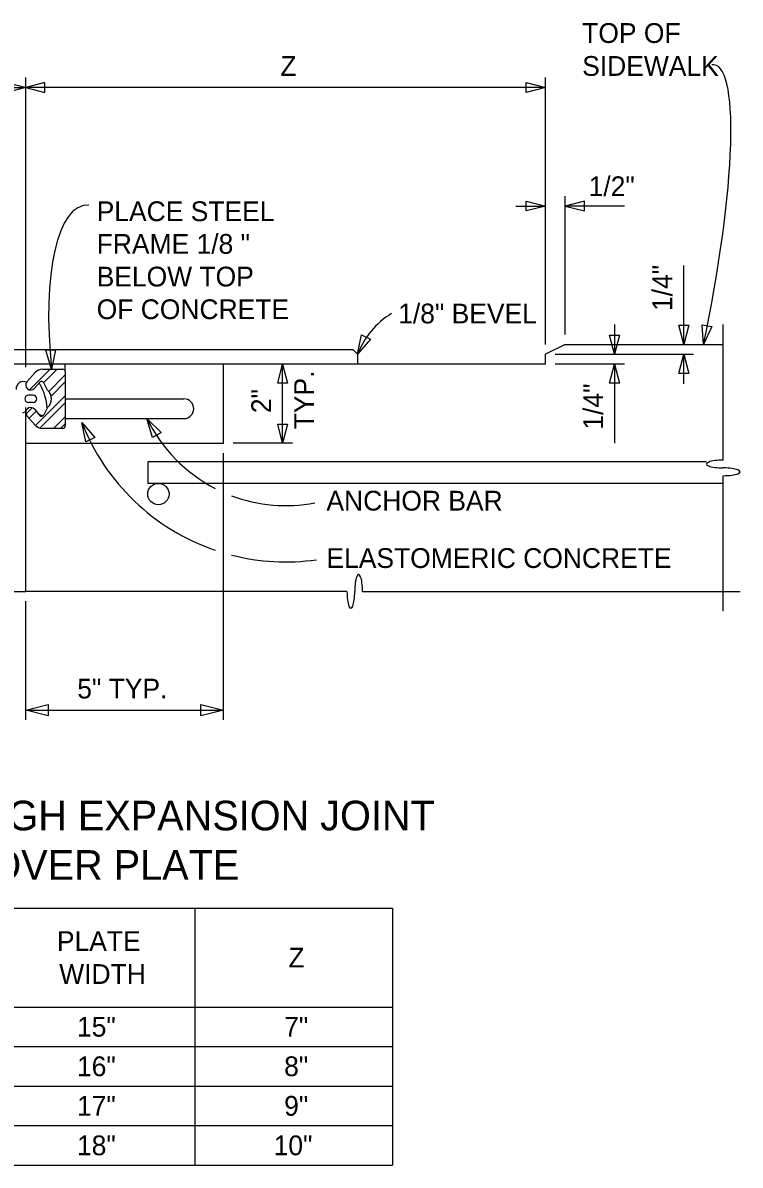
# Model space of a CAD drawing. Extents: x 19590 to 20151, y 19944 to 20103.
# Drawn here: x 19691.75 to 19708.54, y 20042.3 to 20069.02 of the extents above; entities that cross this region are included whole.
import ezdxf

# ---------------------------------------------------------------- set-up
doc = ezdxf.new("R2010")
doc.units = 0
for name, color, linetype in [('Default', 7, 'Continuous'), ('DETAIL_PR', 7, 'Continuous'), ('DETAIL_TEXT_DIMEN_PR', 7, 'Continuous'), ('Level 1', 7, 'Continuous')]:
    doc.layers.add(name, color=color, linetype=linetype)

# ---------------------------------------------------------------- blocks, each defined once
blk = doc.blocks.new('_X7')
at = {"layer": 'Default'}
for p, q in [((8.051, 16.889), (8.594, 17.433)), ((8.426, 17.08), (8.778, 17.433)), ((8.56, 16.847), (8.995, 17.282)), ((8.622, 16.724), (8.995, 17.098)), ((8.213, 15.947), (8.995, 16.729)), ((7.96, 16.247), (8.125, 16.412)), ((8.04, 16.142), (8.224, 16.326)), ((8.329, 15.879), (8.995, 16.545)), ((8.689, 15.87), (8.995, 16.177)), ((8.873, 15.87), (8.995, 15.993))]:
    blk.add_line(p, q, dxfattribs=at)

msp = doc.modelspace()

# ---------------------------------------------------------------- linework, layer by layer
at = {"layer": 'DETAIL_PR'}
for p, q in [((19704.444, 20061.498), (19703.981, 20061.267)), ((19704.444, 20061.498), (19703.981, 20061.267)), ((19704.444, 20061.498), (19708.144, 20061.498)), ((19704.444, 20061.498), (19708.144, 20061.498)), ((19682.937, 20061.383), (19699.472, 20061.383)), ((19682.937, 20061.383), (19699.472, 20061.383)), ((19699.472, 20061.383), (19699.587, 20061.267)), ((19699.472, 20061.383), (19699.587, 20061.267)), ((19699.587, 20061.267), (19699.587, 20061.036)), ((19699.587, 20061.267), (19699.587, 20061.036)), ((19703.981, 20061.036), (19703.981, 20061.267)), ((19703.981, 20061.036), (19703.981, 20061.267)), ((19699.587, 20061.036), (19682.937, 20061.036)), ((19699.587, 20061.036), (19682.937, 20061.036)), ((19692.213, 20060.92), (19692.687, 20060.92)), ((19692.213, 20060.92), (19692.687, 20060.92)), ((19692.745, 20060.862), (19692.745, 20061.036)), ((19692.745, 20060.862), (19692.745, 20061.036)), ((19696.445, 20059.186), (19696.445, 20061.036)), ((19696.445, 20059.186), (19696.445, 20061.036)), ((19703.981, 20061.036), (19699.587, 20061.036)), ((19703.981, 20061.036), (19699.587, 20061.036)), ((19691.849, 20060.626), (19692.04, 20060.842)), ((19691.849, 20060.626), (19692.04, 20060.842)), ((19692.745, 20060.862), (19692.745, 20060.226)), ((19692.745, 20060.862), (19692.745, 20060.226)), ((19692.022, 20060.473), (19692.147, 20060.614)), ((19692.022, 20060.473), (19692.147, 20060.614)), ((19692.328, 20060.43), (19692.242, 20060.602)), ((19692.328, 20060.43), (19692.242, 20060.602)), ((19691.99, 20060.313), (19691.885, 20060.313)), ((19691.99, 20060.313), (19691.885, 20060.313)), ((19691.99, 20060.14), (19691.885, 20060.14)), ((19691.99, 20060.14), (19691.885, 20060.14)), ((19692.745, 20060.226), (19695.52, 20060.226)), ((19692.745, 20060.226), (19692.745, 20059.764)), ((19692.745, 20060.226), (19695.52, 20060.226)), ((19692.745, 20060.226), (19692.745, 20059.764)), ((19691.752, 20059.9), (19691.822, 20059.926)), ((19691.752, 20059.9), (19691.822, 20059.926)), ((19691.82, 20055.72), (19691.82, 20060.019)), ((19691.82, 20055.72), (19691.82, 20060.019)), ((19692.022, 20059.98), (19692.147, 20059.839)), ((19692.022, 20059.98), (19692.147, 20059.839)), ((19692.112, 20059.879), (19692.154, 20059.854)), ((19692.112, 20059.879), (19692.154, 20059.854)), ((19692.328, 20060.023), (19692.242, 20059.851)), ((19692.328, 20060.023), (19692.242, 20059.851)), ((19691.849, 20059.827), (19692.04, 20059.611)), ((19691.849, 20059.827), (19692.04, 20059.611)), ((19692.745, 20059.764), (19695.52, 20059.764)), ((19692.745, 20059.764), (19692.745, 20059.591)), ((19692.745, 20059.764), (19695.52, 20059.764)), ((19692.745, 20059.764), (19692.745, 20059.591)), ((19692.687, 20059.533), (19692.213, 20059.533)), ((19692.687, 20059.533), (19692.213, 20059.533)), ((19691.82, 20059.186), (19696.445, 20059.186)), ((19691.82, 20059.186), (19696.445, 20059.186)), ((19707.749, 20058.748), (19694.675, 20058.748)), ((19694.675, 20058.748), (19694.675, 20058.248)), ((19707.749, 20058.748), (19694.675, 20058.748)), ((19694.675, 20058.748), (19694.675, 20058.248)), ((19708.144, 20058.248), (19694.675, 20058.248)), ((19708.144, 20058.248), (19694.675, 20058.248))]:
    msp.add_line(p, q, dxfattribs=at)
msp.add_circle((19694.925, 20057.998), 0.25, dxfattribs=at)
msp.add_circle((19694.925, 20057.998), 0.25, dxfattribs=at)
for centre, radius, start, end in [((19692.213, 20060.689), 0.231, 90, 138.538), ((19692.213, 20060.689), 0.231, 90, 138.538), ((19692.687, 20060.862), 0.0578, 0, 90), ((19692.687, 20060.862), 0.0578, 0, 90), ((19691.765, 20060.456), 0.173, 64.7625, 184.3545), ((19691.765, 20060.456), 0.173, 64.7625, 184.3545), ((19691.935, 20060.549), 0.116, 138.538, 318.538), ((19691.935, 20060.549), 0.116, 138.538, 318.538), ((19692.107, 20060.533), 0.0578, 28.7472, 73.3345), ((19692.107, 20060.533), 0.0578, 28.7472, 73.3345), ((19692.19, 20060.576), 0.0578, 26.8091, 138.538), ((19692.19, 20060.576), 0.0578, 26.8091, 138.538), ((19690.942, 20059.893), 1.388, 4.9857, 28.7472), ((19690.942, 20059.893), 1.388, 4.9857, 28.7472), ((19692.151, 20060.226), 0.27, 311.1121, 48.8879), ((19692.151, 20060.226), 0.27, 311.1121, 48.8879), ((19691.885, 20060.226), 0.0867, 90, 270), ((19691.885, 20060.226), 0.0867, 90, 270), ((19691.99, 20060.226), 0.0867, 270, 90), ((19691.99, 20060.226), 0.0867, 270, 90), ((19695.52, 20059.995), 0.231, 270, 90), ((19695.52, 20059.995), 0.231, 270, 90), ((19691.935, 20059.904), 0.116, 41.462, 180), ((19691.935, 20059.904), 0.116, 41.462, 180), ((19691.935, 20059.904), 0.116, 180, 221.462), ((19691.935, 20059.904), 0.116, 180, 221.462), ((19692.19, 20059.877), 0.0578, 221.462, 333.1909), ((19692.19, 20059.877), 0.0578, 221.462, 333.1909), ((19692.212, 20059.954), 0.116, 240, 281.5069), ((19692.212, 20059.954), 0.116, 240, 281.5069), ((19692.213, 20059.764), 0.231, 221.462, 270), ((19692.213, 20059.764), 0.231, 221.462, 270), ((19692.687, 20059.591), 0.0578, 270, 0), ((19692.687, 20059.591), 0.0578, 270, 0)]:
    msp.add_arc(centre, radius, start, end, dxfattribs=at)
for centre, major_axis, ratio, start_param, end_param in [((19708.144, 20058.7), (0.395, 0), 0.230204, 1.570796, 4.712389), ((19708.144, 20058.7), (0.395, 0), 0.230204, 1.570796, 4.712389), ((19708.144, 20058.518), (0.395, 0), 0.230206, 4.712389, 7.853982), ((19708.144, 20058.518), (0.395, 0), 0.230206, 4.712389, 7.853982), ((19699.61, 20055.72), (0, -0.395), 0.230204, 1.570796, 4.712389), ((19699.61, 20055.72), (0, -0.395), 0.230204, 1.570796, 4.712389), ((19699.428, 20055.72), (0, -0.395), 0.230206, 4.712389, 7.853982), ((19699.428, 20055.72), (0, -0.395), 0.230206, 4.712389, 7.853982)]:
    msp.add_ellipse(centre, major_axis=major_axis, ratio=ratio, start_param=start_param, end_param=end_param, dxfattribs=at)
at = {"layer": 'DETAIL_TEXT_DIMEN_PR'}
for p, q in [((19691.372, 20067.626), (19691.82, 20067.511)), ((19691.372, 20067.626), (19691.82, 20067.511)), ((19691.82, 20060.967), (19691.82, 20067.742)), ((19691.82, 20060.967), (19691.82, 20067.742)), ((19692.268, 20067.626), (19691.82, 20067.511)), ((19692.268, 20067.626), (19691.82, 20067.511)), ((19692.268, 20067.395), (19692.268, 20067.626)), ((19692.268, 20067.395), (19692.268, 20067.626)), ((19703.533, 20067.395), (19703.533, 20067.626)), ((19703.533, 20067.626), (19703.981, 20067.511)), ((19703.533, 20067.395), (19703.533, 20067.626)), ((19703.533, 20067.626), (19703.981, 20067.511)), ((19703.981, 20061.498), (19703.981, 20067.742)), ((19703.981, 20061.498), (19703.981, 20067.742)), ((19689.412, 20067.511), (19691.82, 20067.511)), ((19689.412, 20067.511), (19691.82, 20067.511)), ((19691.82, 20067.511), (19691.372, 20067.395)), ((19691.82, 20067.511), (19691.372, 20067.395)), ((19703.981, 20067.511), (19691.82, 20067.511)), ((19691.82, 20067.511), (19692.268, 20067.395)), ((19703.981, 20067.511), (19691.82, 20067.511)), ((19691.82, 20067.511), (19692.268, 20067.395)), ((19703.981, 20067.511), (19703.533, 20067.395)), ((19703.981, 20067.511), (19703.533, 20067.395)), ((19704.444, 20061.73), (19704.444, 20064.967)), ((19704.444, 20061.73), (19704.444, 20064.967)), ((19703.533, 20064.62), (19703.533, 20064.851)), ((19703.533, 20064.851), (19703.981, 20064.736)), ((19703.533, 20064.62), (19703.533, 20064.851)), ((19703.533, 20064.851), (19703.981, 20064.736)), ((19703.981, 20064.736), (19703.533, 20064.62)), ((19703.981, 20064.736), (19703.533, 20064.62)), ((19704.892, 20064.851), (19704.444, 20064.736)), ((19704.892, 20064.851), (19704.444, 20064.736)), ((19704.444, 20064.736), (19704.892, 20064.62)), ((19704.444, 20064.736), (19704.892, 20064.62)), ((19704.892, 20064.62), (19704.892, 20064.851)), ((19704.892, 20064.62), (19704.892, 20064.851)), ((19699.587, 20061.267), (19699.679, 20061.721)), ((19699.587, 20061.267), (19699.679, 20061.721)), ((19699.679, 20061.721), (19699.887, 20061.62)), ((19699.679, 20061.721), (19699.887, 20061.62)), ((19705.484, 20061.715), (19705.716, 20061.715)), ((19705.6, 20061.267), (19705.484, 20061.715)), ((19705.484, 20061.715), (19705.716, 20061.715)), ((19705.6, 20061.267), (19705.484, 20061.715)), ((19705.716, 20061.715), (19705.6, 20061.267)), ((19705.716, 20061.715), (19705.6, 20061.267)), ((19707.103, 20061.946), (19707.334, 20061.946)), ((19707.219, 20061.498), (19707.103, 20061.946)), ((19707.103, 20061.946), (19707.334, 20061.946)), ((19707.219, 20061.498), (19707.103, 20061.946)), ((19707.334, 20061.946), (19707.219, 20061.498)), ((19707.334, 20061.946), (19707.219, 20061.498)), ((19707.646, 20061.96), (19707.873, 20061.919)), ((19707.681, 20061.498), (19707.646, 20061.96)), ((19707.646, 20061.96), (19707.873, 20061.919)), ((19707.681, 20061.498), (19707.646, 20061.96)), ((19707.873, 20061.919), (19707.681, 20061.498)), ((19707.873, 20061.919), (19707.681, 20061.498)), ((19708.144, 20058.791), (19708.144, 20061.961)), ((19708.144, 20058.791), (19708.144, 20061.961)), ((19699.887, 20061.62), (19699.587, 20061.267)), ((19699.887, 20061.62), (19699.587, 20061.267)), ((19692.286, 20061.361), (19692.517, 20061.374)), ((19692.286, 20061.361), (19692.517, 20061.374)), ((19692.425, 20060.92), (19692.286, 20061.361)), ((19692.425, 20060.92), (19692.286, 20061.361)), ((19692.517, 20061.374), (19692.425, 20060.92)), ((19692.517, 20061.374), (19692.425, 20060.92)), ((19704.212, 20061.267), (19707.45, 20061.267)), ((19704.212, 20061.267), (19707.45, 20061.267)), ((19707.103, 20060.819), (19707.219, 20061.267)), ((19707.103, 20060.819), (19707.219, 20061.267)), ((19707.219, 20061.267), (19707.334, 20060.819)), ((19707.219, 20061.267), (19707.334, 20060.819)), ((19697.717, 20060.588), (19697.832, 20061.036)), ((19697.717, 20060.588), (19697.832, 20061.036)), ((19697.832, 20059.186), (19697.832, 20061.036)), ((19697.832, 20061.036), (19697.948, 20060.588)), ((19697.832, 20059.186), (19697.832, 20061.036)), ((19697.832, 20061.036), (19697.948, 20060.588)), ((19705.831, 20061.036), (19704.212, 20061.036)), ((19705.831, 20061.036), (19704.212, 20061.036)), ((19705.484, 20060.588), (19705.6, 20061.036)), ((19705.484, 20060.588), (19705.6, 20061.036)), ((19705.6, 20061.036), (19705.716, 20060.588)), ((19705.6, 20061.036), (19705.716, 20060.588)), ((19707.334, 20060.819), (19707.103, 20060.819)), ((19707.334, 20060.819), (19707.103, 20060.819)), ((19697.948, 20060.588), (19697.717, 20060.588)), ((19697.948, 20060.588), (19697.717, 20060.588)), ((19705.716, 20060.588), (19705.484, 20060.588)), ((19705.716, 20060.588), (19705.484, 20060.588)), ((19693.228, 20059.219), (19693.131, 20059.672)), ((19693.131, 20059.672), (19693.435, 20059.323)), ((19693.228, 20059.219), (19693.131, 20059.672)), ((19693.131, 20059.672), (19693.435, 20059.323)), ((19694.788, 20059.32), (19694.657, 20059.764)), ((19694.657, 20059.764), (19694.986, 20059.439)), ((19694.788, 20059.32), (19694.657, 20059.764)), ((19694.657, 20059.764), (19694.986, 20059.439)), ((19697.717, 20059.634), (19697.948, 20059.634)), ((19697.832, 20059.186), (19697.717, 20059.634)), ((19697.717, 20059.634), (19697.948, 20059.634)), ((19697.832, 20059.186), (19697.717, 20059.634)), ((19697.948, 20059.634), (19697.832, 20059.186)), ((19697.948, 20059.634), (19697.832, 20059.186)), ((19693.435, 20059.323), (19693.228, 20059.219)), ((19693.435, 20059.323), (19693.228, 20059.219)), ((19694.986, 20059.439), (19694.788, 20059.32)), ((19694.986, 20059.439), (19694.788, 20059.32)), ((19698.063, 20059.186), (19696.676, 20059.186)), ((19698.063, 20059.186), (19696.676, 20059.186)), ((19696.445, 20052.714), (19696.445, 20058.955)), ((19696.445, 20052.714), (19696.445, 20058.955)), ((19708.144, 20055.258), (19708.144, 20058.427)), ((19708.144, 20055.258), (19708.144, 20058.427)), ((19699.337, 20055.72), (19691.82, 20055.72)), ((19699.337, 20055.72), (19691.82, 20055.72)), ((19699.701, 20055.72), (19708.538, 20055.72)), ((19699.701, 20055.72), (19708.538, 20055.72)), ((19691.82, 20052.714), (19691.82, 20055.489)), ((19691.82, 20052.714), (19691.82, 20055.489)), ((19691.82, 20052.945), (19696.445, 20052.945)), ((19691.82, 20052.945), (19696.445, 20052.945)), ((19686.526, 20048.311), (19700.401, 20048.311)), ((19686.526, 20048.311), (19700.401, 20048.311)), ((19695.776, 20048.311), (19695.776, 20042.298)), ((19695.776, 20048.311), (19695.776, 20042.298)), ((19700.401, 20048.311), (19700.401, 20042.298)), ((19700.401, 20048.311), (19700.401, 20042.298)), ((19686.526, 20045.998), (19700.401, 20045.998)), ((19686.526, 20045.998), (19700.401, 20045.998)), ((19686.526, 20045.073), (19700.401, 20045.073)), ((19686.526, 20045.073), (19700.401, 20045.073)), ((19686.526, 20044.148), (19700.401, 20044.148)), ((19686.526, 20044.148), (19700.401, 20044.148)), ((19686.526, 20043.223), (19700.401, 20043.223)), ((19686.526, 20043.223), (19700.401, 20043.223)), ((19686.526, 20042.298), (19700.401, 20042.298)), ((19686.526, 20042.298), (19700.401, 20042.298))]:
    msp.add_line(p, q, dxfattribs=at)
for centre, radius, start, end in [((19697.907, 20061.539), 5.128, 201.3572, 251.1723), ((19697.907, 20061.539), 5.128, 201.3572, 251.1723), ((19697.907, 20061.339), 3.611, 205.8637, 242.7252), ((19697.907, 20061.339), 3.611, 205.8637, 242.7252), ((19697.907, 20061.339), 3.611, 249.4192, 280.7711), ((19697.907, 20061.339), 3.611, 249.4192, 280.7711), ((19697.907, 20061.539), 5.128, 255.6669, 278.0265), ((19697.907, 20061.539), 5.128, 255.6669, 278.0265)]:
    msp.add_arc(centre, radius, start, end, dxfattribs=at)
msp.add_ellipse((19693.849, 20060.491), major_axis=(-0.659, 4.259), ratio=0.314674, start_param=6.20772, end_param=7.704615, dxfattribs=at)
msp.add_ellipse((19693.849, 20060.491), major_axis=(-0.659, 4.259), ratio=0.314674, start_param=6.20772, end_param=7.704615, dxfattribs=at)
at = {"layer": 'Level 1'}
for p, q in [((19703.287, 20064.736), (19703.981, 20064.736)), ((19703.287, 20064.736), (19703.981, 20064.736)), ((19705.831, 20064.736), (19704.444, 20064.736)), ((19705.831, 20064.736), (19704.444, 20064.736)), ((19707.219, 20061.498), (19707.219, 20063.348)), ((19707.219, 20061.498), (19707.219, 20063.348)), ((19705.6, 20061.961), (19705.6, 20061.267)), ((19705.6, 20061.961), (19705.6, 20061.267)), ((19707.219, 20060.573), (19707.219, 20061.267)), ((19707.219, 20060.573), (19707.219, 20061.267)), ((19705.6, 20061.036), (19705.6, 20059.186)), ((19705.6, 20061.036), (19705.6, 20059.186)), ((19689.412, 20055.72), (19691.82, 20055.72)), ((19689.412, 20055.72), (19691.82, 20055.72)), ((19691.82, 20052.945), (19692.344, 20053.077)), ((19691.82, 20052.945), (19692.344, 20053.077)), ((19692.344, 20052.813), (19691.82, 20052.945)), ((19692.344, 20052.813), (19691.82, 20052.945)), ((19692.344, 20053.077), (19692.344, 20052.813)), ((19692.344, 20053.077), (19692.344, 20052.813)), ((19695.921, 20053.077), (19696.445, 20052.945)), ((19695.921, 20052.813), (19695.921, 20053.077)), ((19695.921, 20053.077), (19696.445, 20052.945)), ((19695.921, 20052.813), (19695.921, 20053.077)), ((19696.445, 20052.945), (19695.921, 20052.813)), ((19696.445, 20052.945), (19695.921, 20052.813))]:
    msp.add_line(p, q, dxfattribs=at)
msp.add_arc((19701.34, 20060.615), 1.87, 120.8358, 159.6044, dxfattribs=at)
msp.add_arc((19701.34, 20060.615), 1.87, 120.8358, 159.6044, dxfattribs=at)
msp.add_ellipse((19706.567, 20061.61), major_axis=(1.377, 6.428), ratio=0.169331, start_param=4.731306, end_param=6.346137, dxfattribs=at)
msp.add_ellipse((19706.567, 20061.61), major_axis=(1.377, 6.428), ratio=0.169331, start_param=4.731306, end_param=6.346137, dxfattribs=at)

# ---------------------------------------------------------------- block references
at = {"layer": 'DETAIL_PR', "xscale": 0.8880107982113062, "yscale": 0.8880107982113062}
msp.add_blockref('_X7', (19684.757, 20045.44), dxfattribs=at)
msp.add_blockref('_X7', (19684.757, 20045.44), dxfattribs=at)

# ---------------------------------------------------------------- texts
at = {"layer": 'DETAIL_TEXT_DIMEN_PR'}
for s, height, p in [('TOP OF', 0.4625, (19704.842, 20068.551)), ('TOP OF', 0.4625, (19704.842, 20068.551)), ('Z', 0.462, (19697.779, 20067.781)), ('Z', 0.462, (19697.779, 20067.781)), ('SIDEWALK', 0.4625, (19704.842, 20067.781)), ('SIDEWALK', 0.4625, (19704.842, 20067.781)), ('PLACE STEEL', 0.4625, (19693.48, 20064.382)), ('PLACE STEEL', 0.4625, (19693.48, 20064.382)), ('FRAME 1/8 " ', 0.4625, (19693.48, 20063.618)), ('FRAME 1/8 " ', 0.4625, (19693.48, 20063.618)), ('BELOW TOP ', 0.4625, (19693.48, 20062.854)), ('BELOW TOP ', 0.4625, (19693.48, 20062.854)), ('OF CONCRETE', 0.4625, (19693.48, 20062.09)), ('OF CONCRETE', 0.4625, (19693.48, 20062.09)), ('1/8" BEVEL', 0.4625, (19700.536, 20061.99)), ('1/8" BEVEL', 0.4625, (19700.536, 20061.99)), ('ANCHOR BAR', 0.4625, (19698.857, 20057.611)), ('ANCHOR BAR', 0.4625, (19698.857, 20057.611)), ('ELASTOMERIC CONCRETE', 0.4625, (19698.857, 20056.269)), ('ELASTOMERIC CONCRETE', 0.4625, (19698.857, 20056.269)), ('5" TYP.', 0.4625, (19693.025, 20053.215)), ('5" TYP.', 0.4625, (19693.025, 20053.215)), ('SECTION THROUGH EXPANSION JOINT', 0.69385, (19683.71, 20050.13)), ('SECTION THROUGH EXPANSION JOINT', 0.69385, (19683.71, 20050.13)), ('AND COVER PLATE', 0.69385, (19688.104, 20048.974)), ('AND COVER PLATE', 0.69385, (19688.104, 20048.974))]:
    msp.add_text(s, height=height, dxfattribs=at).set_placement(p)
for s, height, rotation, p in [('1/2"', 0.4625, 360, (19704.993, 20064.967)), ('1/2"', 0.4625, 360, (19704.993, 20064.967)), ('1/4"', 0.4625, 90, (19706.949, 20062.279)), ('1/4"', 0.4625, 90, (19706.949, 20062.279)), ('TYP.', 0.4625, 90, (19698.564, 20059.512)), ('TYP.', 0.4625, 90, (19698.564, 20059.512)), ('2"', 0.4625, 90, (19697.562, 20059.89)), ('2"', 0.4625, 90, (19697.562, 20059.89)), ('1/4"', 0.4625, 90, (19705.33, 20059.504)), ('1/4"', 0.4625, 90, (19705.33, 20059.504)), ('PLATE', 0.4625, 0, (19692.549, 20047.309)), ('PLATE', 0.4625, 0, (19692.549, 20047.309)), ('Z', 0.462, 0, (19697.967, 20046.923)), ('Z', 0.462, 0, (19697.967, 20046.923)), ('WIDTH', 0.4625, 0, (19692.603, 20046.538)), ('WIDTH', 0.4625, 0, (19692.603, 20046.538)), ('15"', 0.4625, 0, (19693.019, 20045.305)), ('15"', 0.4625, 0, (19693.019, 20045.305)), ('7"', 0.4625, 0, (19697.867, 20045.305)), ('7"', 0.4625, 0, (19697.867, 20045.305)), ('16"', 0.4625, 0, (19693.019, 20044.38)), ('16"', 0.4625, 0, (19693.019, 20044.38)), ('8"', 0.4625, 0, (19697.867, 20044.38)), ('8"', 0.4625, 0, (19697.867, 20044.38)), ('17"', 0.4625, 0, (19693.019, 20043.455)), ('17"', 0.4625, 0, (19693.019, 20043.455)), ('9"', 0.4625, 0, (19697.867, 20043.455)), ('9"', 0.4625, 0, (19697.867, 20043.455)), ('18"', 0.4625, 0, (19693.019, 20042.53)), ('18"', 0.4625, 0, (19693.019, 20042.53)), ('10"', 0.4625, 0, (19697.621, 20042.53)), ('10"', 0.4625, 0, (19697.621, 20042.53))]:
    msp.add_text(s, height=height, rotation=rotation, dxfattribs=at).set_placement(p)

doc.saveas('drawing.dxf')
